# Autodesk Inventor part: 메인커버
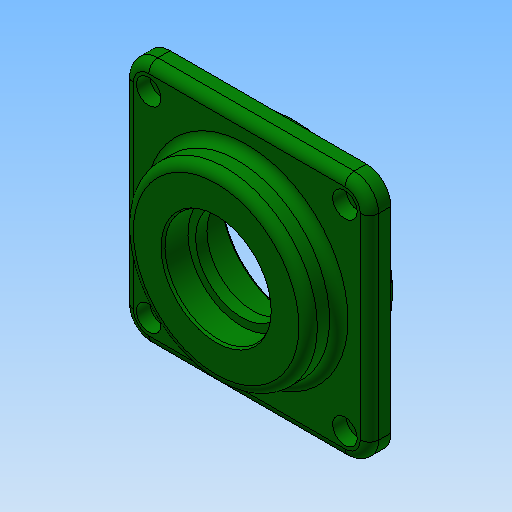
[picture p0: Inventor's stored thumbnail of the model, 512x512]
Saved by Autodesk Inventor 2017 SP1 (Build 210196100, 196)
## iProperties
Created: 2018-09
Part Number: 메인커버
Material: 알루미늄 6061
Document SubType Name: Modeling
Designer: mduedu
Density: 2.71 g/cm^3
Mass: 178.493 g
Surface Area: 197.445 cm^2
Volume: 65.8646 cm^3
Appearance: 진녹색
Author: mduedu
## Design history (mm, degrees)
sketch "스케치1"
  geometry: L1 (-40, -40)-(40, -40); L2 (40, -40)-(40, 40); L3 (40, 40)-(-40, 40); L4 (-40, 40)-(-40, -40); L5 (-40, -40)-(40, 40); L6 (40, -40)-(-40, 40); 1 further point
  constraints: 12 end point, 2 midpoint, 2 parallel, 1 horizontal, 1 perpendicular
  dimensions: "d0" = 80 distance of L3.end L2.end; "d1" = 80 distance of L2.end L1.end
extrude "돌출1" new body sketch "스케치1" distance "d2" = 7; taper "d3" = 0 deg
sketch "스케치2"
  geometry: C1 r 30 at (0, 0); 1 further point
  constraints: 1 centre point, 1 coincident
  dimensions: "d4" = 60 diameter of C1
extrude "돌출2" join sketch "스케치2" distance "d5" = 10; taper "d6" = 0 deg
sketch "스케치3"
  geometry: C1 r 32.5 at (0, 0); 1 further point
  constraints: 1 centre point, 1 coincident
  dimensions: "d7" = 65 diameter of C1
extrude "돌출3" join sketch "스케치3" distance "d8" = 9; taper "d9" = 0 deg
sketch "스케치4"
  geometry: L1 (-32.5, -9)-(32.5, -9) reference; L2 (30, 17)-(-30, 17) reference; L3 (0, 17)-(0, -9); L4 (0, -9)-(23.5, -9); L5 (23.5, -9)-(23.5, 5); L6 (23.5, 5)-(0, 5); L7 (0, 5)-(0, -9); L8 (0, 5)-(15, 5); L9 (15, 5)-(15, 8.7); L10 (15, 8.7)-(0, 8.7); L11 (0, 8.7)-(0, 5); L12 (0, 8.7)-(17.5, 8.7); L13 (17.5, 8.7)-(17.5, 17); L14 (17.5, 17)-(0, 17); L15 (0, 17)-(0, 8.7); 1 further point
  constraints: 26 end point, 6 parallel, 3 horizontal, 3 perpendicular, 2 midpoint, 1 point on line
  dimensions: "d10" = 14 distance of L4.end L5.end; "d12" = 8.3 distance of L12.end L13.end; "d13" = 35 diameter of L13 L3; "d14" = 30 diameter of L9 L3; "d15" = 47 diameter of L5 L3
revolve "회전1" sketch "스케치4" stored, may be unused: angle "d16" = 90 deg
fillet "모깎기1" dims "d17" = 8
fillet "모깎기2" dims "d18" = 3
fillet "모깎기3" dims "d19" = 3
chamfer "모따기1" distance "d20" = 0.8; stored, may be unused: second distance "d21" = 2, angle "d22" = 30 deg
chamfer "모따기2" distance "d23" = 1; stored, may be unused: second distance "d24" = 2, angle "d25" = 30 deg
fillet "모깎기4" dims "d26" = 0.3
sketch "스케치5"
  geometry: A1 r 8 centre (-32, 32) between (-32, 40) and (-40, 32) reference; A2 r 8 centre (-32, -32) between (-40, -32) and (-32, -40) reference; A3 r 8 centre (32, -32) between (32, -40) and (40, -32) reference; A4 r 8 centre (32, 32) between (40, 32) and (32, 40) reference; 5 further points
  constraints: 4 coincident
hole "구멍1" sketch "스케치5" at (-32, 32), (32, 32), (32, -32), (-32, -32) diameter "d27" = 4.5; stored, may be unused: countersink angle "d31" = 90 deg, drill point angle "d33" = 118 deg; dims "d28" = 6, "d29" = 8, "d30" = 4.4, "d32" = 8
fillet "모깎기5" dims "d34" = 0.5
node "솔리드1"
